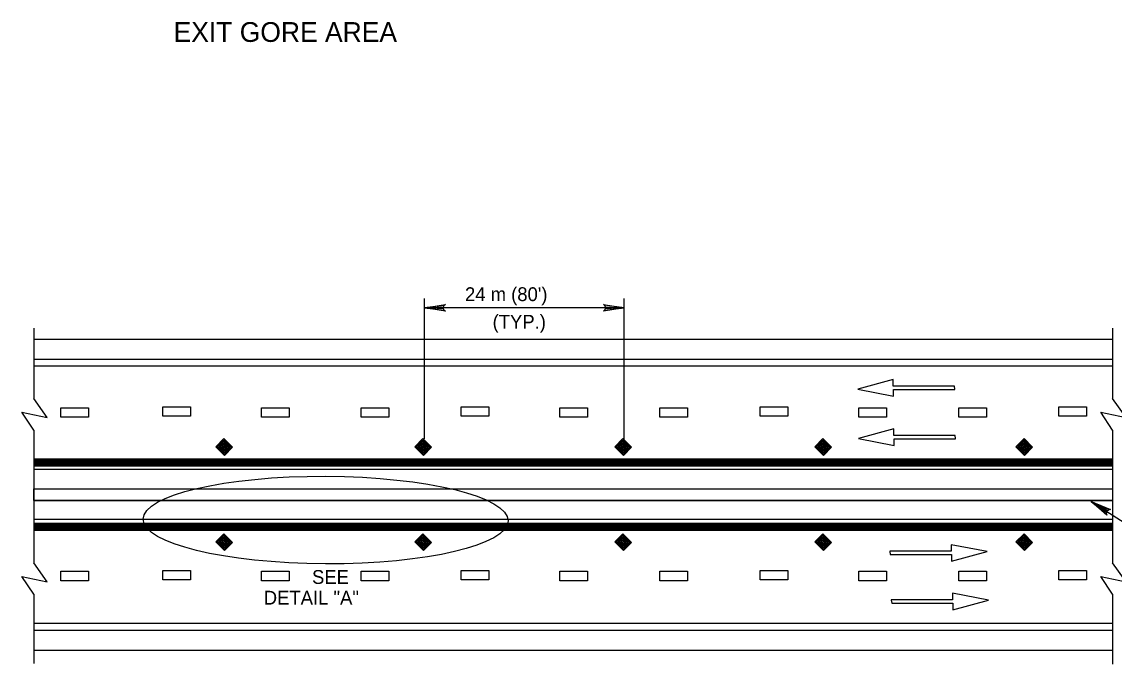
# Model space of a CAD drawing. Extents: x 639362 to 641108, y 298458 to 299646.
# Drawn here: x 639604.4 to 639841.8, y 299307.7 to 299447.4 of the extents above; entities that cross this region are included whole.
import ezdxf

# ---------------------------------------------------------------- set-up
doc = ezdxf.new("R2010")
doc.units = 0
doc.layers.add('2', color=7, linetype='Continuous')

msp = doc.modelspace()

# ---------------------------------------------------------------- linework, layer by layer
at = {"layer": '2'}
for p, q in [((639691.87, 299356.71), (639691.87, 299387.2)), ((639735.31, 299356.49), (639735.31, 299387.2)), ((639735.31, 299385.2), (639691.87, 299385.2)), ((639606.93, 299380.78), (639606.93, 299365.49)), ((639841.43, 299380.77), (639841.43, 299365.49)), ((639606.93, 299378.41), (639841.43, 299378.41)), ((639606.93, 299374.06), (639841.43, 299374.06)), ((639606.93, 299372.56), (639841.43, 299372.56)), ((639793.76, 299369.59), (639786.04, 299367.47)), ((639793.76, 299368.14), (639793.76, 299369.59)), ((639786.04, 299367.47), (639793.84, 299365.99)), ((639807.09, 299368.14), (639793.76, 299368.14)), ((639793.84, 299365.99), (639793.84, 299367.44)), ((639793.84, 299367.44), (639807.17, 299367.44)), ((639807.17, 299367.47), (639807.09, 299368.14)), ((639807.17, 299367.44), (639807.17, 299367.47)), ((639609.88, 299361.36), (639606.93, 299365.49)), ((639844.38, 299361.36), (639841.43, 299365.49)), ((639606.93, 299358.62), (639604.35, 299362.49)), ((639604.35, 299362.49), (639609.88, 299361.36)), ((639612.82, 299361.41), (639612.82, 299363.47)), ((639612.82, 299363.47), (639618.83, 299363.47)), ((639618.83, 299363.47), (639618.83, 299361.41)), ((639635.01, 299361.6), (639635.01, 299363.66)), ((639635.01, 299363.66), (639641.02, 299363.66)), ((639641.02, 299361.6), (639635.01, 299361.6)), ((639641.02, 299363.66), (639641.02, 299361.6)), ((639656.45, 299361.41), (639656.45, 299363.47)), ((639656.45, 299363.47), (639662.47, 299363.47)), ((639662.47, 299363.47), (639662.47, 299361.41)), ((639678.08, 299361.41), (639678.08, 299363.47)), ((639678.08, 299363.47), (639684.1, 299363.47)), ((639684.1, 299363.47), (639684.1, 299361.41)), ((639699.87, 299361.6), (639699.87, 299363.66)), ((639699.87, 299363.66), (639705.88, 299363.66)), ((639705.88, 299361.6), (639699.87, 299361.6)), ((639705.88, 299363.66), (639705.88, 299361.6)), ((639721.32, 299361.41), (639721.32, 299363.47)), ((639721.32, 299363.47), (639727.34, 299363.47)), ((639727.34, 299363.47), (639727.34, 299361.41)), ((639743.04, 299361.41), (639743.04, 299363.47)), ((639743.04, 299363.47), (639749.06, 299363.47)), ((639749.06, 299363.47), (639749.06, 299361.41)), ((639764.85, 299361.6), (639764.85, 299363.66)), ((639764.85, 299363.66), (639770.87, 299363.66)), ((639770.87, 299361.6), (639764.85, 299361.6)), ((639770.87, 299363.66), (639770.87, 299361.6)), ((639786.3, 299361.41), (639786.3, 299363.47)), ((639786.3, 299363.47), (639792.31, 299363.47)), ((639792.31, 299363.47), (639792.31, 299361.41)), ((639808, 299361.41), (639808, 299363.47)), ((639808, 299363.47), (639814.01, 299363.47)), ((639814.01, 299363.47), (639814.01, 299361.41)), ((639829.77, 299361.6), (639829.77, 299363.66)), ((639829.77, 299363.66), (639835.78, 299363.66)), ((639835.78, 299361.6), (639829.77, 299361.6)), ((639835.78, 299363.66), (639835.78, 299361.6)), ((639841.43, 299358.62), (639838.86, 299362.49)), ((639838.86, 299362.49), (639844.38, 299361.36)), ((639618.83, 299361.41), (639612.82, 299361.41)), ((639662.47, 299361.41), (639656.45, 299361.41)), ((639684.1, 299361.41), (639678.08, 299361.41)), ((639727.34, 299361.41), (639721.32, 299361.41)), ((639749.06, 299361.41), (639743.04, 299361.41)), ((639792.31, 299361.41), (639786.3, 299361.41)), ((639814.01, 299361.41), (639808, 299361.41)), ((639606.93, 299358.62), (639606.93, 299340.83)), ((639793.91, 299358.88), (639786.19, 299356.76)), ((639793.91, 299357.43), (639793.91, 299358.88)), ((639807.24, 299357.43), (639793.91, 299357.43)), ((639807.32, 299356.76), (639807.24, 299357.43)), ((639841.43, 299358.62), (639841.43, 299329.76)), ((639646.5, 299354.98), (639648.27, 299356.75)), ((639648.38, 299353.1), (639646.5, 299354.98)), ((639646.72, 299355.02), (639648.23, 299356.52)), ((639648.42, 299353.32), (639646.72, 299355.02)), ((639646.98, 299355.02), (639648.23, 299356.27)), ((639648.42, 299353.58), (639646.98, 299355.02)), ((639647.23, 299355.02), (639648.23, 299356.02)), ((639648.42, 299353.83), (639647.23, 299355.02)), ((639647.48, 299355.02), (639648.23, 299355.77)), ((639648.42, 299354.08), (639647.48, 299355.02)), ((639647.73, 299355.02), (639648.23, 299355.52)), ((639648.42, 299354.33), (639647.73, 299355.02)), ((639647.98, 299355.02), (639648.23, 299355.27)), ((639648.42, 299354.58), (639647.98, 299355.02)), ((639648.23, 299356.52), (639649.92, 299354.83)), ((639648.23, 299356.27), (639649.67, 299354.83)), ((639648.23, 299356.02), (639649.42, 299354.83)), ((639648.23, 299355.77), (639649.17, 299354.83)), ((639648.23, 299355.52), (639648.92, 299354.83)), ((639648.23, 299355.27), (639648.67, 299354.83)), ((639648.23, 299355.02), (639648.42, 299354.83)), ((639648.27, 299356.75), (639650.14, 299354.87)), ((639650.14, 299354.87), (639648.38, 299353.1)), ((639649.92, 299354.83), (639648.42, 299353.32)), ((639649.67, 299354.83), (639648.42, 299353.58)), ((639649.42, 299354.83), (639648.42, 299353.83)), ((639649.17, 299354.83), (639648.42, 299354.08)), ((639648.92, 299354.83), (639648.42, 299354.33)), ((639648.67, 299354.83), (639648.42, 299354.58)), ((639689.76, 299354.98), (639691.53, 299356.75)), ((639691.64, 299353.1), (639689.76, 299354.98)), ((639689.99, 299355.02), (639691.49, 299356.52)), ((639691.68, 299353.32), (639689.99, 299355.02)), ((639690.24, 299355.02), (639691.49, 299356.27)), ((639691.68, 299353.58), (639690.24, 299355.02)), ((639690.49, 299355.02), (639691.49, 299356.02)), ((639691.68, 299353.83), (639690.49, 299355.02)), ((639690.74, 299355.02), (639691.49, 299355.77)), ((639691.68, 299354.08), (639690.74, 299355.02)), ((639690.99, 299355.02), (639691.49, 299355.52)), ((639691.68, 299354.33), (639690.99, 299355.02)), ((639691.24, 299355.02), (639691.49, 299355.27)), ((639691.68, 299354.58), (639691.24, 299355.02)), ((639691.49, 299356.52), (639693.18, 299354.83)), ((639691.49, 299356.27), (639692.94, 299354.83)), ((639691.49, 299356.02), (639692.68, 299354.83)), ((639691.49, 299355.77), (639692.43, 299354.83)), ((639691.49, 299355.52), (639692.18, 299354.83)), ((639691.49, 299355.27), (639691.93, 299354.83)), ((639691.49, 299355.02), (639691.68, 299354.83)), ((639691.53, 299356.75), (639693.4, 299354.87)), ((639693.4, 299354.87), (639691.64, 299353.1)), ((639693.18, 299354.83), (639691.68, 299353.32)), ((639692.94, 299354.83), (639691.68, 299353.58)), ((639692.68, 299354.83), (639691.68, 299353.83)), ((639692.43, 299354.83), (639691.68, 299354.08)), ((639692.18, 299354.83), (639691.68, 299354.33)), ((639691.93, 299354.83), (639691.68, 299354.58)), ((639733.23, 299354.98), (639735, 299356.75)), ((639735.11, 299353.1), (639733.23, 299354.98)), ((639733.46, 299355.02), (639734.96, 299356.52)), ((639735.15, 299353.32), (639733.46, 299355.02)), ((639733.71, 299355.02), (639734.97, 299356.27)), ((639735.15, 299353.58), (639733.71, 299355.02)), ((639733.96, 299355.02), (639734.97, 299356.02)), ((639735.15, 299353.83), (639733.96, 299355.02)), ((639734.21, 299355.02), (639734.97, 299355.77)), ((639735.15, 299354.08), (639734.21, 299355.02)), ((639734.46, 299355.02), (639734.96, 299355.52)), ((639735.15, 299354.33), (639734.46, 299355.02)), ((639734.71, 299355.02), (639734.96, 299355.27)), ((639735.15, 299354.58), (639734.71, 299355.02)), ((639734.96, 299356.52), (639736.66, 299354.83)), ((639734.96, 299355.52), (639735.65, 299354.83)), ((639734.96, 299355.27), (639735.4, 299354.83)), ((639734.96, 299355.02), (639735.15, 299354.83)), ((639734.97, 299356.27), (639736.41, 299354.83)), ((639734.97, 299356.02), (639736.16, 299354.83)), ((639734.97, 299355.77), (639735.91, 299354.83)), ((639735, 299356.75), (639736.88, 299354.87)), ((639736.88, 299354.87), (639735.11, 299353.1)), ((639736.66, 299354.83), (639735.15, 299353.32)), ((639736.41, 299354.83), (639735.15, 299353.58)), ((639736.16, 299354.83), (639735.15, 299353.83)), ((639735.91, 299354.83), (639735.15, 299354.08)), ((639735.65, 299354.83), (639735.15, 299354.33)), ((639735.4, 299354.83), (639735.15, 299354.58)), ((639776.71, 299354.98), (639778.47, 299356.75)), ((639778.58, 299353.1), (639776.71, 299354.98)), ((639776.93, 299355.02), (639778.44, 299356.52)), ((639778.62, 299353.32), (639776.93, 299355.02)), ((639777.18, 299355.02), (639778.44, 299356.27)), ((639778.62, 299353.58), (639777.18, 299355.02)), ((639777.43, 299355.02), (639778.44, 299356.02)), ((639778.62, 299353.83), (639777.43, 299355.02)), ((639777.69, 299355.02), (639778.44, 299355.77)), ((639778.62, 299354.08), (639777.69, 299355.02)), ((639777.94, 299355.02), (639778.44, 299355.52)), ((639778.62, 299354.33), (639777.94, 299355.02)), ((639778.19, 299355.02), (639778.44, 299355.27)), ((639778.63, 299354.58), (639778.19, 299355.02)), ((639778.43, 299355.02), (639778.62, 299354.83)), ((639778.44, 299356.52), (639780.13, 299354.83)), ((639778.44, 299356.27), (639779.88, 299354.83)), ((639778.44, 299356.02), (639779.63, 299354.83)), ((639778.44, 299355.77), (639779.38, 299354.83)), ((639778.44, 299355.52), (639779.13, 299354.83)), ((639778.44, 299355.27), (639778.88, 299354.83)), ((639778.47, 299356.75), (639780.35, 299354.87)), ((639780.35, 299354.87), (639778.58, 299353.1)), ((639780.13, 299354.83), (639778.62, 299353.32)), ((639779.88, 299354.83), (639778.62, 299353.58)), ((639779.63, 299354.83), (639778.62, 299353.83)), ((639779.38, 299354.83), (639778.62, 299354.08)), ((639779.13, 299354.83), (639778.62, 299354.33)), ((639778.88, 299354.83), (639778.63, 299354.58)), ((639786.19, 299356.76), (639793.99, 299355.28)), ((639793.99, 299355.28), (639793.99, 299356.73)), ((639793.99, 299356.73), (639807.32, 299356.73)), ((639807.32, 299356.73), (639807.32, 299356.76)), ((639820.43, 299354.98), (639822.2, 299356.75)), ((639822.31, 299353.1), (639820.43, 299354.98)), ((639820.66, 299355.02), (639822.16, 299356.52)), ((639822.35, 299353.32), (639820.66, 299355.02)), ((639820.91, 299355.02), (639822.16, 299356.27)), ((639822.35, 299353.58), (639820.91, 299355.02)), ((639821.16, 299355.02), (639822.16, 299356.02)), ((639822.35, 299353.83), (639821.16, 299355.02)), ((639821.41, 299355.02), (639822.16, 299355.77)), ((639822.35, 299354.08), (639821.41, 299355.02)), ((639821.66, 299355.02), (639822.16, 299355.52)), ((639822.35, 299354.33), (639821.66, 299355.02)), ((639821.91, 299355.02), (639822.16, 299355.27)), ((639822.35, 299354.58), (639821.91, 299355.02)), ((639822.16, 299356.52), (639823.85, 299354.83)), ((639822.16, 299356.27), (639823.61, 299354.83)), ((639822.16, 299356.02), (639823.35, 299354.83)), ((639822.16, 299355.77), (639823.1, 299354.83)), ((639822.16, 299355.52), (639822.85, 299354.83)), ((639822.16, 299355.27), (639822.6, 299354.83)), ((639822.16, 299355.02), (639822.35, 299354.83)), ((639822.2, 299356.75), (639824.07, 299354.87)), ((639824.07, 299354.87), (639822.31, 299353.1)), ((639823.85, 299354.83), (639822.35, 299353.32)), ((639823.61, 299354.83), (639822.35, 299353.58)), ((639823.35, 299354.83), (639822.35, 299353.83)), ((639823.1, 299354.83), (639822.35, 299354.08)), ((639822.85, 299354.83), (639822.35, 299354.33)), ((639822.6, 299354.83), (639822.35, 299354.58)), ((639606.93, 299352.33), (639841.43, 299352.33)), ((639606.93, 299352.18), (639841.43, 299352.18)), ((639606.93, 299352.03), (639841.43, 299352.03)), ((639606.93, 299351.88), (639841.43, 299351.88)), ((639606.93, 299351.73), (639841.43, 299351.73)), ((639606.93, 299351.58), (639841.43, 299351.58)), ((639606.93, 299351.43), (639841.43, 299351.43)), ((639606.93, 299351.28), (639841.43, 299351.28)), ((639606.93, 299351.13), (639841.43, 299351.13)), ((639606.93, 299350.98), (639841.43, 299350.98)), ((639606.93, 299350.83), (639841.43, 299350.83)), ((639606.93, 299350.08), (639841.43, 299350.08)), ((639606.93, 299345.83), (639841.43, 299345.83)), ((639606.93, 299343.33), (639606.93, 299329.76)), ((639606.93, 299343.33), (639841.43, 299343.33)), ((639836.76, 299343.11), (639851.76, 299333.52)), ((639606.93, 299339.23), (639841.43, 299339.23)), ((639606.93, 299338.33), (639841.43, 299338.33)), ((639606.93, 299338.33), (639841.43, 299338.33)), ((639606.93, 299338.33), (639841.43, 299338.33)), ((639606.93, 299338.18), (639841.43, 299338.18)), ((639606.93, 299338.03), (639841.43, 299338.03)), ((639606.93, 299337.88), (639841.43, 299337.88)), ((639606.93, 299337.73), (639841.43, 299337.73)), ((639606.93, 299337.58), (639841.43, 299337.58)), ((639606.93, 299337.43), (639841.43, 299337.43)), ((639606.93, 299337.28), (639841.43, 299337.28)), ((639606.93, 299337.13), (639841.43, 299337.13)), ((639606.93, 299336.98), (639841.43, 299336.98)), ((639606.93, 299336.83), (639841.43, 299336.83)), ((639646.5, 299334.3), (639648.27, 299336.07)), ((639646.72, 299334.34), (639648.23, 299335.84)), ((639646.98, 299334.34), (639648.23, 299335.6)), ((639648.23, 299335.84), (639649.92, 299334.15)), ((639648.23, 299335.6), (639649.67, 299334.15)), ((639648.27, 299336.07), (639650.14, 299334.19)), ((639689.76, 299334.3), (639691.53, 299336.07)), ((639689.99, 299334.34), (639691.49, 299335.84)), ((639690.24, 299334.34), (639691.49, 299335.6)), ((639691.49, 299335.84), (639693.18, 299334.15)), ((639691.49, 299335.6), (639692.94, 299334.15)), ((639691.53, 299336.07), (639693.4, 299334.19)), ((639733.23, 299334.3), (639735, 299336.07)), ((639733.46, 299334.34), (639734.96, 299335.84)), ((639733.71, 299334.34), (639734.97, 299335.6)), ((639734.96, 299335.84), (639736.66, 299334.15)), ((639734.97, 299335.6), (639736.41, 299334.15)), ((639735, 299336.07), (639736.88, 299334.19)), ((639776.71, 299334.3), (639778.47, 299336.07)), ((639776.93, 299334.34), (639778.44, 299335.84)), ((639777.18, 299334.34), (639778.44, 299335.6)), ((639778.44, 299335.84), (639780.13, 299334.15)), ((639778.44, 299335.6), (639779.88, 299334.15)), ((639778.47, 299336.07), (639780.35, 299334.19)), ((639820.43, 299334.3), (639822.2, 299336.07)), ((639820.66, 299334.34), (639822.16, 299335.84)), ((639820.91, 299334.34), (639822.16, 299335.6)), ((639822.16, 299335.84), (639823.85, 299334.15)), ((639822.16, 299335.6), (639823.61, 299334.15)), ((639822.2, 299336.07), (639824.07, 299334.19)), ((639648.38, 299332.43), (639646.5, 299334.3)), ((639648.42, 299332.65), (639646.72, 299334.34)), ((639648.42, 299332.9), (639646.98, 299334.34)), ((639647.23, 299334.34), (639648.23, 299335.34)), ((639648.42, 299333.15), (639647.23, 299334.34)), ((639647.48, 299334.34), (639648.23, 299335.09)), ((639648.42, 299333.4), (639647.48, 299334.34)), ((639647.73, 299334.34), (639648.23, 299334.84)), ((639648.42, 299333.65), (639647.73, 299334.34)), ((639647.98, 299334.34), (639648.23, 299334.59)), ((639648.42, 299333.9), (639647.98, 299334.34)), ((639648.23, 299335.34), (639649.42, 299334.15)), ((639648.23, 299335.09), (639649.17, 299334.15)), ((639648.23, 299334.84), (639648.92, 299334.15)), ((639648.23, 299334.59), (639648.67, 299334.15)), ((639648.23, 299334.34), (639648.42, 299334.15)), ((639650.14, 299334.19), (639648.38, 299332.43)), ((639649.92, 299334.15), (639648.42, 299332.65)), ((639649.67, 299334.15), (639648.42, 299332.9)), ((639649.42, 299334.15), (639648.42, 299333.15)), ((639649.17, 299334.15), (639648.42, 299333.4)), ((639648.92, 299334.15), (639648.42, 299333.65)), ((639648.67, 299334.15), (639648.42, 299333.9)), ((639691.64, 299332.43), (639689.76, 299334.3)), ((639691.68, 299332.65), (639689.99, 299334.34)), ((639691.68, 299332.9), (639690.24, 299334.34)), ((639690.49, 299334.34), (639691.49, 299335.34)), ((639691.68, 299333.15), (639690.49, 299334.34)), ((639690.74, 299334.34), (639691.49, 299335.09)), ((639691.68, 299333.4), (639690.74, 299334.34)), ((639690.99, 299334.34), (639691.49, 299334.84)), ((639691.68, 299333.65), (639690.99, 299334.34)), ((639691.24, 299334.34), (639691.49, 299334.59)), ((639691.68, 299333.9), (639691.24, 299334.34)), ((639691.49, 299335.34), (639692.68, 299334.15)), ((639691.49, 299335.09), (639692.43, 299334.15)), ((639691.49, 299334.84), (639692.18, 299334.15)), ((639691.49, 299334.59), (639691.93, 299334.15)), ((639691.49, 299334.34), (639691.68, 299334.15)), ((639693.4, 299334.19), (639691.64, 299332.43)), ((639693.18, 299334.15), (639691.68, 299332.65)), ((639692.94, 299334.15), (639691.68, 299332.9)), ((639692.68, 299334.15), (639691.68, 299333.15)), ((639692.43, 299334.15), (639691.68, 299333.4)), ((639692.18, 299334.15), (639691.68, 299333.65)), ((639691.93, 299334.15), (639691.68, 299333.9)), ((639735.11, 299332.43), (639733.23, 299334.3)), ((639735.15, 299332.65), (639733.46, 299334.34)), ((639735.15, 299332.9), (639733.71, 299334.34)), ((639733.96, 299334.34), (639734.97, 299335.34)), ((639735.15, 299333.15), (639733.96, 299334.34)), ((639734.21, 299334.34), (639734.97, 299335.09)), ((639735.15, 299333.4), (639734.21, 299334.34)), ((639734.46, 299334.34), (639734.96, 299334.84)), ((639735.15, 299333.65), (639734.46, 299334.34)), ((639734.71, 299334.34), (639734.96, 299334.59)), ((639735.15, 299333.9), (639734.71, 299334.34)), ((639734.96, 299334.84), (639735.65, 299334.15)), ((639734.96, 299334.59), (639735.4, 299334.15)), ((639734.96, 299334.34), (639735.15, 299334.15)), ((639734.97, 299335.34), (639736.16, 299334.15)), ((639734.97, 299335.09), (639735.91, 299334.15)), ((639736.88, 299334.19), (639735.11, 299332.43)), ((639736.66, 299334.15), (639735.15, 299332.65)), ((639736.41, 299334.15), (639735.15, 299332.9)), ((639736.16, 299334.15), (639735.15, 299333.15)), ((639735.91, 299334.15), (639735.15, 299333.4)), ((639735.65, 299334.15), (639735.15, 299333.65)), ((639735.4, 299334.15), (639735.15, 299333.9)), ((639778.58, 299332.43), (639776.71, 299334.3)), ((639778.62, 299332.65), (639776.93, 299334.34)), ((639778.62, 299332.9), (639777.18, 299334.34)), ((639777.43, 299334.34), (639778.44, 299335.34)), ((639778.62, 299333.15), (639777.43, 299334.34)), ((639777.69, 299334.34), (639778.44, 299335.09)), ((639778.62, 299333.4), (639777.69, 299334.34)), ((639777.94, 299334.34), (639778.44, 299334.84)), ((639778.62, 299333.65), (639777.94, 299334.34)), ((639778.19, 299334.34), (639778.44, 299334.59)), ((639778.63, 299333.9), (639778.19, 299334.34)), ((639778.43, 299334.34), (639778.62, 299334.15)), ((639778.44, 299335.34), (639779.63, 299334.15)), ((639778.44, 299335.09), (639779.38, 299334.15)), ((639778.44, 299334.84), (639779.13, 299334.15)), ((639778.44, 299334.59), (639778.88, 299334.15)), ((639780.35, 299334.19), (639778.58, 299332.43)), ((639780.13, 299334.15), (639778.62, 299332.65)), ((639779.88, 299334.15), (639778.62, 299332.9)), ((639779.63, 299334.15), (639778.62, 299333.15)), ((639779.38, 299334.15), (639778.62, 299333.4)), ((639779.13, 299334.15), (639778.62, 299333.65)), ((639778.88, 299334.15), (639778.63, 299333.9)), ((639814.17, 299332.21), (639806.37, 299333.68)), ((639806.37, 299333.68), (639806.37, 299332.24)), ((639822.31, 299332.43), (639820.43, 299334.3)), ((639822.35, 299332.65), (639820.66, 299334.34)), ((639822.35, 299332.9), (639820.91, 299334.34)), ((639821.16, 299334.34), (639822.16, 299335.34)), ((639822.35, 299333.15), (639821.16, 299334.34)), ((639821.41, 299334.34), (639822.16, 299335.09)), ((639822.35, 299333.4), (639821.41, 299334.34)), ((639821.66, 299334.34), (639822.16, 299334.84)), ((639822.35, 299333.65), (639821.66, 299334.34)), ((639821.91, 299334.34), (639822.16, 299334.59)), ((639822.35, 299333.9), (639821.91, 299334.34)), ((639822.16, 299335.34), (639823.35, 299334.15)), ((639822.16, 299335.09), (639823.1, 299334.15)), ((639822.16, 299334.84), (639822.85, 299334.15)), ((639822.16, 299334.59), (639822.6, 299334.15)), ((639822.16, 299334.34), (639822.35, 299334.15)), ((639824.07, 299334.19), (639822.31, 299332.43)), ((639823.85, 299334.15), (639822.35, 299332.65)), ((639823.61, 299334.15), (639822.35, 299332.9)), ((639823.35, 299334.15), (639822.35, 299333.15)), ((639823.1, 299334.15), (639822.35, 299333.4)), ((639822.85, 299334.15), (639822.35, 299333.65)), ((639822.6, 299334.15), (639822.35, 299333.9)), ((639793.04, 299332.24), (639793.04, 299332.21)), ((639806.37, 299332.24), (639793.04, 299332.24)), ((639793.04, 299332.21), (639793.12, 299331.53)), ((639793.12, 299331.53), (639806.45, 299331.53)), ((639806.45, 299330.09), (639814.17, 299332.21)), ((639806.45, 299331.53), (639806.45, 299330.09)), ((639609.88, 299325.62), (639606.93, 299329.76)), ((639844.38, 299325.62), (639841.43, 299329.76)), ((639606.93, 299322.89), (639604.35, 299326.76)), ((639604.35, 299326.76), (639609.88, 299325.62)), ((639612.82, 299325.83), (639612.82, 299327.9)), ((639612.82, 299327.9), (639618.83, 299327.9)), ((639618.83, 299327.9), (639618.83, 299325.83)), ((639635.01, 299326.02), (639635.01, 299328.09)), ((639635.01, 299328.09), (639641.02, 299328.09)), ((639641.02, 299326.02), (639635.01, 299326.02)), ((639641.02, 299328.09), (639641.02, 299326.02)), ((639656.45, 299325.83), (639656.45, 299327.9)), ((639656.45, 299327.9), (639662.47, 299327.9)), ((639662.47, 299327.9), (639662.47, 299325.83)), ((639678.08, 299325.83), (639678.08, 299327.9)), ((639678.08, 299327.9), (639684.1, 299327.9)), ((639684.1, 299327.9), (639684.1, 299325.83)), ((639699.87, 299326.02), (639699.87, 299328.09)), ((639699.87, 299328.09), (639705.88, 299328.09)), ((639705.88, 299326.02), (639699.87, 299326.02)), ((639705.88, 299328.09), (639705.88, 299326.02)), ((639721.32, 299325.83), (639721.32, 299327.9)), ((639721.32, 299327.9), (639727.34, 299327.9)), ((639727.34, 299327.9), (639727.34, 299325.83)), ((639743.04, 299325.83), (639743.04, 299327.9)), ((639743.04, 299327.9), (639749.06, 299327.9)), ((639749.06, 299327.9), (639749.06, 299325.83)), ((639764.85, 299326.02), (639764.85, 299328.09)), ((639764.85, 299328.09), (639770.87, 299328.09)), ((639770.87, 299326.02), (639764.85, 299326.02)), ((639770.87, 299328.09), (639770.87, 299326.02)), ((639786.3, 299325.83), (639786.3, 299327.9)), ((639786.3, 299327.9), (639792.31, 299327.9)), ((639792.31, 299327.9), (639792.31, 299325.83)), ((639808, 299325.83), (639808, 299327.9)), ((639808, 299327.9), (639814.01, 299327.9)), ((639814.01, 299327.9), (639814.01, 299325.83)), ((639829.77, 299326.02), (639829.77, 299328.09)), ((639829.77, 299328.09), (639835.78, 299328.09)), ((639835.78, 299326.02), (639829.77, 299326.02)), ((639835.78, 299328.09), (639835.78, 299326.02)), ((639841.43, 299322.89), (639838.86, 299326.76)), ((639838.86, 299326.76), (639844.38, 299325.62)), ((639618.83, 299325.83), (639612.82, 299325.83)), ((639662.47, 299325.83), (639656.45, 299325.83)), ((639684.1, 299325.83), (639678.08, 299325.83)), ((639727.34, 299325.83), (639721.32, 299325.83)), ((639749.06, 299325.83), (639743.04, 299325.83)), ((639792.31, 299325.83), (639786.3, 299325.83)), ((639814.01, 299325.83), (639808, 299325.83)), ((639606.93, 299322.89), (639606.93, 299307.82)), ((639793.35, 299321.67), (639793.35, 299321.64)), ((639806.68, 299321.67), (639793.35, 299321.67)), ((639793.35, 299321.64), (639793.43, 299320.97)), ((639814.48, 299321.64), (639806.68, 299323.12)), ((639806.68, 299323.12), (639806.68, 299321.67)), ((639806.76, 299319.52), (639814.48, 299321.64)), ((639841.43, 299322.89), (639841.43, 299307.7)), ((639793.43, 299320.97), (639806.76, 299320.97)), ((639806.76, 299320.97), (639806.76, 299319.52)), ((639606.93, 299316.59), (639841.43, 299316.59)), ((639606.93, 299315.09), (639841.43, 299315.09)), ((639606.93, 299310.74), (639841.43, 299310.74))]:
    msp.add_line(p, q, dxfattribs=at)
for points in [[(639696.19, 299384.66), (639696.03, 299384.97), (639691.87, 299385.2), (639696.19, 299384.66), (639696.41, 299384.47), (639691.87, 299385.2), (639696.03, 299385.41), (639696.18, 299385.72), (639691.87, 299385.2), (639696.41, 299385.93), (639696.18, 299385.72)], [(639730.99, 299385.75), (639731.15, 299385.43), (639735.31, 299385.2), (639730.99, 299385.75), (639730.77, 299385.93), (639735.31, 299385.2), (639731.16, 299385), (639731.01, 299384.69), (639735.31, 299385.2), (639730.77, 299384.48), (639731.01, 299384.69)], [(639840.14, 299340.36), (639840.17, 299340.71), (639836.76, 299343.11), (639840.14, 299340.36), (639840.23, 299340.08), (639836.76, 299343.11), (639840.4, 299341.09), (639840.69, 299341.27), (639836.76, 299343.11), (639841, 299341.32), (639840.69, 299341.27)]]:
    msp.add_lwpolyline(points, dxfattribs=at)
msp.add_lwpolyline([(639606.93, 299345.83), (639841.43, 299345.83), (639841.43, 299343.33), (639606.93, 299343.33)], close=True, dxfattribs=at)
msp.add_ellipse((639670.39, 299339.04), major_axis=(39.66, -0.17), ratio=0.240157, dxfattribs=at)

# ---------------------------------------------------------------- texts
for s, height, p in [('EXIT GORE AREA', 4.3, (639637.34, 299443.02)), ("24 m (80')", 3, (639700.68, 299386.66)), ('(TYP.)', 3, (639706.68, 299380.66)), ('SEE', 3, (639667.43, 299325.16)), ('DETAIL "A"', 3, (639656.94, 299320.66))]:
    msp.add_text(s, height=height, dxfattribs=at).set_placement(p)

doc.saveas('drawing.dxf')
